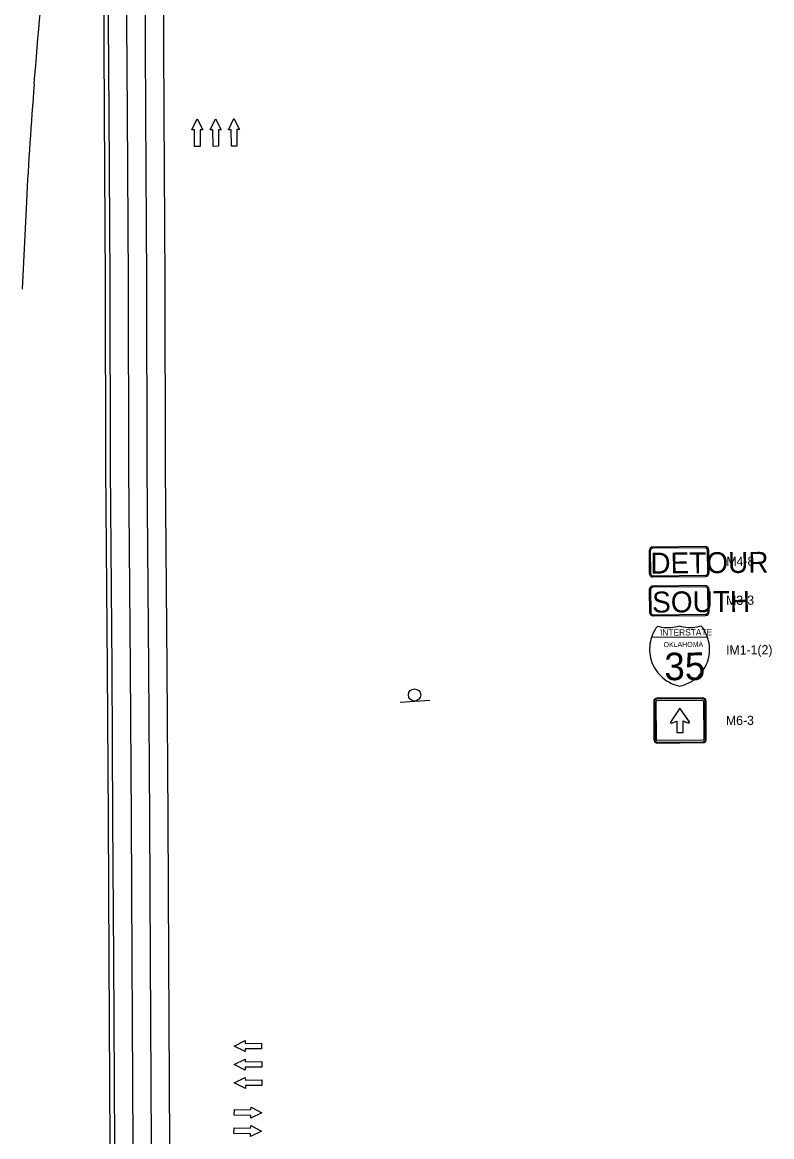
# Model space of a CAD drawing. Extents: x 2135767 to 2151731, y 141839 to 175894.
# Drawn here: x 2150708 to 2151198, y 145614 to 146342 of the extents above; entities that cross this region are included whole.
import ezdxf

# ---------------------------------------------------------------- set-up
doc = ezdxf.new("R2010")
doc.units = 0
for name, color, linetype in [('PR_Phasing_Detour_1', 7, 'Continuous'), ('PR_Phasing_Traffic_Barrier_Phase_1', 7, 'Continuous'), ('PR_Phasing_Traffic_Striping_Dashed_Phase_1', 7, 'Continuous'), ('PR_Phasing_Traffic_Striping_White_Phase_1', 7, 'Continuous'), ('PR_Phasing_Traffic_Striping_Yellow_Phase_1', 7, 'Continuous'), ('Pr_Traffic_Arrows_Phase_1', 7, 'Continuous')]:
    doc.layers.add(name, color=color, linetype=linetype)

msp = doc.modelspace()

# ---------------------------------------------------------------- linework, layer by layer
at = {"layer": 'PR_Phasing_Detour_1'}
for p, q in [((2151117.95, 145997.08), (2151118.07, 145982.42)), ((2151118.76, 145997.08), (2151118.88, 145982.43)), ((2151154.56, 145999.81), (2151120.37, 145999.54)), ((2151154.56, 145999), (2151120.38, 145998.72)), ((2151156.32, 145982.73), (2151156.21, 145997.38)), ((2151157.14, 145982.74), (2151157.02, 145997.39)), ((2151120.52, 145980.82), (2151154.71, 145981.09)), ((2151154.69, 145974.36), (2151120.5, 145974.08)), ((2151154.7, 145973.54), (2151120.51, 145973.27)), ((2151120.53, 145980), (2151154.72, 145980.28)), ((2151118.08, 145971.62), (2151118.2, 145956.97)), ((2151118.89, 145971.63), (2151119.01, 145956.97)), ((2151156.45, 145957.28), (2151156.34, 145971.93)), ((2151157.27, 145957.28), (2151157.15, 145971.93)), ((2151120.65, 145955.36), (2151154.84, 145955.63)), ((2151120.66, 145954.55), (2151154.85, 145954.82)), ((2151119.21, 145940.61), (2151156.4, 145940.91)), ((2151152.97, 145901.08), (2151123.11, 145900.84)), ((2151152.97, 145900.47), (2151123.11, 145900.23)), ((2151152.97, 145900.47), (2151123.11, 145900.23)), ((2150955.33, 145898.31), (2150964.96, 145898.91)), ((2150964.96, 145898.91), (2150974.59, 145899.52)), ((2151120.96, 145898.66), (2151121.16, 145873.69)), ((2151121.57, 145898.67), (2151121.77, 145873.69)), ((2151121.57, 145898.67), (2151121.77, 145873.69)), ((2151122.79, 145873.7), (2151122.59, 145898.68)), ((2151122.79, 145873.7), (2151122.59, 145898.68)), ((2151123.12, 145899.22), (2151152.98, 145899.46)), ((2151123.12, 145899.22), (2151152.98, 145899.46)), ((2151138.09, 145894.25), (2151131.92, 145885.18)), ((2151144.41, 145885.28), (2151138.09, 145894.25)), ((2151153.52, 145898.92), (2151153.72, 145873.95)), ((2151153.52, 145898.92), (2151153.72, 145873.95)), ((2151154.74, 145873.96), (2151154.54, 145898.93)), ((2151154.74, 145873.96), (2151154.54, 145898.93)), ((2151155.35, 145873.96), (2151155.15, 145898.94)), ((2151132.62, 145884.49), (2151136.08, 145885.91)), ((2151136.08, 145885.91), (2151136.14, 145878.36)), ((2151140.3, 145878.39), (2151140.24, 145885.94)), ((2151140.24, 145885.94), (2151143.72, 145884.58)), ((2151153.19, 145873.41), (2151123.33, 145873.17)), ((2151153.19, 145873.41), (2151123.33, 145873.17)), ((2151123.34, 145872.15), (2151153.2, 145872.39)), ((2151123.34, 145872.15), (2151153.2, 145872.39)), ((2151123.35, 145871.54), (2151153.2, 145871.78)), ((2151136.14, 145878.36), (2151140.3, 145878.39))]:
    msp.add_line(p, q, dxfattribs=at)
for points in [[(2151123.38, 145947.71), (2151122.47, 145946.45), (2151121.63, 145945.14), (2151120.88, 145943.77), (2151120.23, 145942.36), (2151119.66, 145940.91), (2151119.18, 145939.43), (2151118.81, 145937.92), (2151118.52, 145936.39), (2151118.34, 145934.84), (2151118.26, 145933.29), (2151118.27, 145931.73), (2151118.38, 145930.18), (2151118.6, 145928.63), (2151118.91, 145927.11), (2151119.31, 145925.6), (2151119.82, 145924.13), (2151120.41, 145922.69), (2151121.1, 145921.29), (2151121.87, 145919.94), (2151122.73, 145918.64), (2151123.67, 145917.4), (2151124.68, 145916.22), (2151125.77, 145915.11), (2151126.93, 145914.07), (2151128.15, 145913.1), (2151129.43, 145912.22), (2151130.76, 145911.41), (2151132.15, 145910.7), (2151133.57, 145910.07), (2151135.04, 145909.54), (2151136.53, 145909.1), (2151138.05, 145908.76), (2151139.56, 145909.12), (2151141.05, 145909.59), (2151142.5, 145910.14), (2151143.92, 145910.79), (2151145.29, 145911.53), (2151146.61, 145912.35), (2151147.88, 145913.26), (2151149.08, 145914.24), (2151150.22, 145915.3), (2151151.3, 145916.43), (2151152.29, 145917.63), (2151153.21, 145918.89), (2151154.05, 145920.2), (2151154.8, 145921.56), (2151155.46, 145922.97), (2151156.03, 145924.42), (2151156.51, 145925.9), (2151156.89, 145927.41), (2151157.18, 145928.94), (2151157.37, 145930.49), (2151157.46, 145932.04), (2151157.45, 145933.6), (2151157.34, 145935.15), (2151157.13, 145936.7), (2151156.82, 145938.22), (2151156.42, 145939.73), (2151155.92, 145941.2), (2151155.33, 145942.64), (2151154.65, 145944.04), (2151153.88, 145945.4), (2151153.02, 145946.7), (2151152.09, 145947.94), (2151150.69, 145947.55), (2151149.26, 145947.23), (2151147.83, 145947), (2151146.38, 145946.86), (2151144.92, 145946.81), (2151143.46, 145946.84), (2151142.01, 145946.96), (2151140.57, 145947.16), (2151139.14, 145947.45), (2151137.73, 145947.83), (2151136.33, 145947.43), (2151134.91, 145947.12), (2151133.47, 145946.89), (2151132.02, 145946.75), (2151130.57, 145946.69), (2151129.11, 145946.72), (2151127.66, 145946.84), (2151126.22, 145947.05), (2151124.79, 145947.34), (2151123.38, 145947.71)], [(2151138.09, 145894.22), (2151131.92, 145885.15)], [(2151144.41, 145885.25), (2151138.09, 145894.22)], [(2151132.62, 145884.46), (2151136.08, 145885.88), (2151136.14, 145878.33), (2151140.3, 145878.36), (2151140.24, 145885.91), (2151143.72, 145884.55)]]:
    msp.add_lwpolyline(points, dxfattribs=at)
msp.add_circle((2150964.71, 145902.91), 4, dxfattribs=at)
for centre, radius, start, end in [((2151120.39, 145997.1), 2.44, 90.46107, 180.46107), ((2151120.39, 145997.1), 1.63, 90.46107, 180.46107), ((2151154.58, 145997.37), 2.44, 0.46107, 90.46107), ((2151154.58, 145997.37), 1.63, 0.46107, 90.46107), ((2151120.51, 145982.44), 2.44, 180.46107, 270.46107), ((2151120.51, 145982.44), 1.63, 180.46107, 270.46107), ((2151154.7, 145982.72), 1.63, 270.46107, 0.46107), ((2151154.7, 145982.72), 2.44, 270.46107, 0.46107), ((2151120.52, 145971.64), 2.44, 90.46107, 180.46107), ((2151120.52, 145971.64), 1.63, 90.46107, 180.46107), ((2151154.71, 145971.91), 2.44, 0.46107, 90.46107), ((2151154.71, 145971.91), 1.63, 0.46107, 90.46107), ((2151120.64, 145956.99), 2.44, 180.46107, 270.46107), ((2151120.64, 145956.99), 1.63, 180.46107, 270.46107), ((2151154.83, 145957.26), 1.63, 270.46107, 0.46107), ((2151154.83, 145957.26), 2.44, 270.46107, 0.46107), ((2151123.13, 145898.68), 2.16, 90.46107, 180.46107), ((2151152.99, 145898.92), 2.16, 0.46107, 90.46107), ((2151152.99, 145898.92), 1.55, 0.46107, 90.46107), ((2151152.98, 145898.92), 1.55, 0.46107, 90.46107), ((2151123.13, 145898.68), 1.55, 90.46107, 180.46107), ((2151123.13, 145898.68), 1.55, 90.46107, 180.46107), ((2151123.13, 145898.68), 0.537, 90.46107, 180.46107), ((2151123.13, 145898.68), 0.537, 90.46107, 180.46107), ((2151152.99, 145898.92), 0.537, 0.46107, 90.46107), ((2151152.98, 145898.92), 0.537, 0.46107, 90.46107), ((2151132.61, 145885.18), 0.694, 180.46107, 270.46107), ((2151132.62, 145885.16), 0.694, 180.46107, 270.46107), ((2151143.71, 145885.27), 0.694, 270.46107, 0.46107), ((2151143.72, 145885.25), 0.694, 270.46107, 0.46107), ((2151123.33, 145873.7), 2.16, 180.46107, 270.46107), ((2151123.33, 145873.7), 1.55, 180.46107, 270.46107), ((2151123.33, 145873.7), 1.55, 180.46107, 270.46107), ((2151123.33, 145873.7), 0.537, 180.46107, 270.46107), ((2151123.33, 145873.7), 0.537, 180.46107, 270.46107), ((2151153.19, 145873.95), 0.537, 270.46107, 0.46107), ((2151153.19, 145873.95), 0.537, 270.46107, 0.46107), ((2151153.19, 145873.95), 2.16, 270.46107, 0.46107), ((2151153.19, 145873.95), 1.55, 270.46107, 0.46107), ((2151153.19, 145873.95), 1.55, 270.46107, 0.46107)]:
    msp.add_arc(centre, radius, start, end, dxfattribs=at)
at = {"layer": 'PR_Phasing_Traffic_Barrier_Phase_1'}
msp.add_line((2150711.08, 146225.3), (2150708.38, 146168.01), dxfattribs=at)
for points in [[(2150767.45, 146662.17), (2150763.61, 146524.79), (2150763.49, 146520.33), (2150762.33, 146475.14), (2150761.37, 146372.8), (2150761.84, 146282.68), (2150762.58, 146173.1), (2150762.81, 146051.01), (2150763.85, 145920.4), (2150764.43, 145822.04), (2150764.95, 145730.37), (2150765.18, 145690.17)], [(2150765.18, 145690.17), (2150765.87, 145568.57), (2150766.69, 145456.49), (2150767.25, 145365.88), (2150767.65, 145260.61), (2150768.52, 145130.54), (2150769.07, 145042.71), (2150769.65, 144930.44), (2150770.69, 144766.95), (2150771.26, 144659.72), (2150771.35, 144642.77), (2150771.7, 144580.84)]]:
    msp.add_lwpolyline(points, dxfattribs=at)
for centre, radius, start, end in [((2154239.46, 146028.83), 3534.05, 174.01627, 175.56826), ((2153764.27, 146062.76), 3057.51, 175.51401, 176.95264)]:
    msp.add_arc(centre, radius, start, end, dxfattribs=at)
at = {"layer": 'PR_Phasing_Traffic_Striping_Dashed_Phase_1'}
for points in [[(2150788.16, 146739.66), (2150783.69, 146661.92), (2150779.71, 146568.33), (2150777.32, 146474.88), (2150776.37, 146372.77), (2150776.84, 146282.77), (2150777.58, 146173.16), (2150777.81, 146051.08), (2150778.85, 145920.51), (2150779.43, 145822.12), (2150779.95, 145730.45), (2150780.18, 145690.3)], [(2150800.14, 146738.93), (2150795.68, 146661.32), (2150791.7, 146567.92), (2150789.32, 146474.67), (2150788.37, 146372.74), (2150788.84, 146282.84), (2150789.58, 146173.21), (2150789.81, 146051.14), (2150790.85, 145920.59), (2150791.43, 145822.19), (2150791.95, 145730.52), (2150792.18, 145690.37)], [(2150780.18, 145690.3), (2150780.87, 145568.67), (2150781.69, 145456.59), (2150782.25, 145365.95), (2150782.65, 145260.69), (2150783.52, 145130.64), (2150784.07, 145042.8), (2150784.65, 144930.53), (2150785.69, 144767.03), (2150786.17, 144667.55), (2150786.79, 144583.05)], [(2150792.18, 145690.37), (2150792.87, 145568.75), (2150793.69, 145456.67), (2150794.25, 145366.01), (2150794.65, 145260.76), (2150795.52, 145130.72), (2150796.07, 145042.87), (2150796.65, 144930.6), (2150797.69, 144767.1), (2150798.17, 144667.62), (2150798.79, 144582.71)]]:
    msp.add_lwpolyline(points, dxfattribs=at)
at = {"layer": 'PR_Phasing_Traffic_Striping_White_Phase_1'}
for points in [[(2150776.18, 146740.39), (2150771.71, 146662.52), (2150767.71, 146568.74), (2150765.33, 146475.09), (2150764.37, 146372.79), (2150764.84, 146282.7), (2150765.58, 146173.11), (2150765.81, 146051.02), (2150766.85, 145920.42), (2150767.43, 145822.06), (2150767.95, 145730.38), (2150768.18, 145690.22)], [(2150768.18, 145690.19), (2150768.87, 145568.59), (2150769.69, 145456.51), (2150770.25, 145365.89), (2150770.65, 145260.63), (2150771.52, 145130.56), (2150772.07, 145042.73), (2150772.65, 144930.46), (2150773.69, 144766.97), (2150774.17, 144667.47), (2150774.79, 144582.12)]]:
    msp.add_lwpolyline(points, dxfattribs=at)
at = {"layer": 'PR_Phasing_Traffic_Striping_Yellow_Phase_1'}
for points in [[(2150812.11, 146738.2), (2150807.66, 146660.73), (2150803.69, 146567.51), (2150801.32, 146474.47), (2150800.37, 146372.72), (2150800.84, 146282.91), (2150801.58, 146173.27), (2150801.81, 146051.2), (2150802.85, 145920.67), (2150803.43, 145822.26), (2150803.95, 145730.59), (2150804.18, 145690.43)], [(2150804.18, 145690.44), (2150804.87, 145568.83), (2150805.69, 145456.75), (2150806.25, 145366.07), (2150806.65, 145260.82), (2150807.52, 145130.8), (2150808.07, 145042.94), (2150808.65, 144930.67), (2150809.69, 144767.17), (2150810.17, 144667.69), (2150810.51, 144576.41)]]:
    msp.add_lwpolyline(points, dxfattribs=at)
at = {"layer": 'Pr_Traffic_Arrows_Phase_1'}
for p, q in [((2150819.14, 146271.94), (2150822.69, 146279.16)), ((2150822.69, 146279.16), (2150826.34, 146271.99)), ((2150831.14, 146272.02), (2150834.69, 146279.24)), ((2150834.69, 146279.24), (2150838.34, 146272.07)), ((2150843.14, 146272.1), (2150846.69, 146279.32)), ((2150846.69, 146279.32), (2150850.34, 146272.14)), ((2150820.94, 146271.95), (2150819.14, 146271.94)), ((2150821.01, 146261.15), (2150820.94, 146271.95)), ((2150826.34, 146271.99), (2150824.54, 146271.98)), ((2150824.54, 146271.98), (2150824.61, 146261.18)), ((2150832.94, 146272.03), (2150831.14, 146272.02)), ((2150833.01, 146261.23), (2150832.94, 146272.03)), ((2150838.34, 146272.07), (2150836.54, 146272.05)), ((2150836.54, 146272.05), (2150836.61, 146261.25)), ((2150844.94, 146272.11), (2150843.14, 146272.1)), ((2150845.01, 146261.31), (2150844.94, 146272.11)), ((2150850.34, 146272.14), (2150848.54, 146272.13)), ((2150848.54, 146272.13), (2150848.61, 146261.33)), ((2150824.61, 146261.18), (2150821.01, 146261.15)), ((2150836.61, 146261.25), (2150833.01, 146261.23)), ((2150848.61, 146261.33), (2150845.01, 146261.31)), ((2150846.76, 145673.52), (2150853.93, 145677.17)), ((2150853.93, 145677.17), (2150853.94, 145675.37)), ((2150853.94, 145675.37), (2150864.74, 145675.45)), ((2150864.74, 145675.45), (2150864.77, 145671.85)), ((2150853.98, 145669.97), (2150846.76, 145673.52)), ((2150864.77, 145671.85), (2150853.97, 145671.77)), ((2150853.97, 145671.77), (2150853.98, 145669.97)), ((2150846.85, 145661.52), (2150854.02, 145665.17)), ((2150854.08, 145657.97), (2150846.85, 145661.52)), ((2150854.02, 145665.17), (2150854.04, 145663.37)), ((2150854.04, 145663.37), (2150864.84, 145663.45)), ((2150864.84, 145663.45), (2150864.86, 145659.86)), ((2150846.94, 145649.52), (2150854.11, 145653.17)), ((2150864.86, 145659.86), (2150854.06, 145659.77)), ((2150854.06, 145659.77), (2150854.08, 145657.97)), ((2150854.11, 145653.17), (2150854.13, 145651.37)), ((2150854.17, 145645.97), (2150846.94, 145649.52)), ((2150854.13, 145651.37), (2150864.93, 145651.46)), ((2150864.96, 145647.86), (2150854.16, 145647.77)), ((2150854.16, 145647.77), (2150854.17, 145645.97)), ((2150864.93, 145651.46), (2150864.96, 145647.86)), ((2150846.94, 145628.56), (2150847.01, 145632.15)), ((2150847.01, 145632.15), (2150857.81, 145631.96)), ((2150857.81, 145631.96), (2150857.84, 145633.76)), ((2150857.84, 145633.76), (2150864.97, 145630.03)), ((2150857.74, 145628.36), (2150846.94, 145628.56)), ((2150864.97, 145630.03), (2150857.71, 145626.56)), ((2150857.71, 145626.56), (2150857.74, 145628.36)), ((2150846.72, 145616.56), (2150846.79, 145620.16)), ((2150857.52, 145616.36), (2150846.72, 145616.56)), ((2150846.79, 145620.16), (2150857.59, 145619.96)), ((2150864.75, 145618.03), (2150857.49, 145614.56)), ((2150857.59, 145619.96), (2150857.62, 145621.76)), ((2150857.62, 145621.76), (2150864.75, 145618.03)), ((2150857.49, 145614.56), (2150857.52, 145616.36))]:
    msp.add_line(p, q, dxfattribs=at)

# ---------------------------------------------------------------- texts
at = {"layer": 'PR_Phasing_Detour_1'}
for s, height, p in [('DETOUR', 13.675, (2151118.83, 145982.16)), ('M4-8', 6, (2151168.44, 145987.16)), ('SOUTH', 13.675, (2151120, 145956.71)), ('M3-3', 6, (2151168.32, 145961.7)), ('INTERSTATE', 4.084, (2151125.15, 145941.65)), ('OKLAHOMA', 3.31, (2151127.39, 145934.15)), ('35', 17.974, (2151127.98, 145912.52)), ('IM1-1(2)', 6, (2151168.28, 145929.25)), ('M6-3', 6, (2151168.18, 145883.27))]:
    msp.add_text(s, height=height, rotation=0.46107, dxfattribs=at).set_placement(p)

doc.saveas('drawing.dxf')
